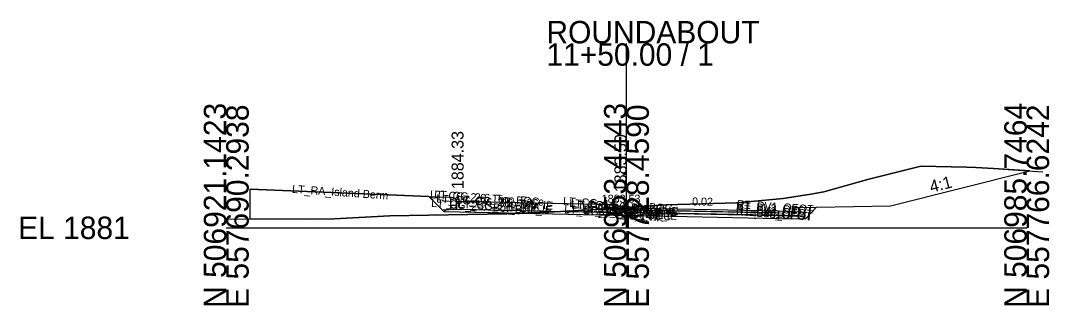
# Model space of a CAD drawing. Extents: x -36 to 140, y -10 to 2515.
# Drawn here: x -35.7 to 92.8, y 1490.3 to 1525.9 of the extents above; entities that cross this region are included whole.
import ezdxf

# ---------------------------------------------------------------- set-up
doc = ezdxf.new("R2010")
doc.units = 0
for name, color, linetype in [('Default', 7, 'Continuous'), ('Exist Cross Section Cell', 7, 'Continuous'), ('Exist XS Center Line Elevation Label', 7, 'Continuous'), ('Exist XS Ground Line', 7, 'Continuous'), ('Prop CMT Conc Surface', 7, 'Continuous'), ('Prop CMT Concrete Structures', 7, 'Continuous'), ('Prop CMT Pvmt Course 1', 7, 'Continuous'), ('Prop CMT Pvmt Course 1 CG', 7, 'Continuous'), ('Prop CMT Pvmt Course 2', 7, 'Continuous'), ('Prop CMT Pvmt Course 3', 7, 'Continuous'), ('Prop CMT Pvmt Course 4', 7, 'Continuous'), ('Prop CMT Slope Grass', 7, 'Continuous'), ('Prop CMT Subgrade Earthwork', 7, 'Continuous'), ('Prop Conc 4in Sidewalk', 7, 'Continuous'), ('Prop Conc Curb and Gutter', 7, 'Continuous'), ('Prop XS Earthwork Shape', 7, 'Continuous'), ('Prop XS Finish Grade Earthwork', 7, 'Continuous'), ('Prop XS Hydro Elevations', 7, 'Continuous'), ('Prop XS Side Slope Text', 7, 'Continuous'), ('Typical Structure Recommendation Sheet 1 CELL', 7, 'Continuous')]:
    doc.layers.add(name, color=color, linetype=linetype)

msp = doc.modelspace()

# ---------------------------------------------------------------- linework, layer by layer
at = {"layer": 'Exist Cross Section Cell'}
for p, q in [((40, 1500), (40, 1523.04)), ((-10, 1500), (40, 1500)), ((40, 1500), (90, 1500))]:
    msp.add_line(p, q, dxfattribs=at)
at = {"layer": 'Exist XS Ground Line'}
msp.add_lwpolyline([(-10, 1501.12), (0.01, 1501.08), (3.49, 1501.11), (10.45, 1501.51), (25.07, 1501.74), (30.26, 1501.97), (36.25, 1502.27), (40, 1502.53), (44.96, 1502.86), (53.77, 1503.13), (59.56, 1503.65), (63.04, 1504.2), (64.65, 1504.51), (70.29, 1506.06), (76.77, 1507.68), (82.46, 1507.56), (83.66, 1507.53), (85.87, 1507.39), (92.03, 1507)], dxfattribs=at)
at = {"layer": 'Prop CMT Conc Surface'}
for p, q in [((18.65, 1503.61), (18, 1503.82)), ((18, 1503.82), (18, 1502.82)), ((18, 1502.82), (18.75, 1502.82)), ((18, 1502.82), (18, 1502.32)), ((18.75, 1502.82), (18.75, 1503.47)), ((18.75, 1502.32), (18.75, 1502.82)), ((38.5, 1501.91), (38.5, 1502.91)), ((39.19, 1502.68), (38.5, 1502.91)), ((38.65, 1502.74), (38.56, 1502.74)), ((38.56, 1502.74), (38.64, 1502.66)), ((38.64, 1502.66), (38.65, 1502.74)), ((39.25, 1502.59), (39.25, 1502.6)), ((17.2, 1502.02), (17.5, 1502.32)), ((18, 1502.32), (17.5, 1502.32)), ((18, 1502.32), (18.75, 1502.32)), ((40, 1501.91), (38.5, 1501.91)), ((38.59, 1502.12), (38.52, 1502.11)), ((38.52, 1502.11), (38.55, 1502)), ((38.55, 1502), (38.59, 1502.12)), ((38.84, 1502.44), (38.89, 1502.29)), ((38.93, 1502.38), (38.84, 1502.44)), ((38.89, 1502.29), (38.93, 1502.38)), ((39.15, 1502.15), (39.24, 1502.1)), ((39.18, 1502.02), (39.15, 1502.15)), ((39.24, 1502.1), (39.18, 1502.02)), ((40, 1502.5), (39.34, 1502.5)), ((39.51, 1502.11), (39.43, 1502.09)), ((39.43, 1502.09), (39.47, 1501.98)), ((39.47, 1501.98), (39.51, 1502.11)), ((39.76, 1502.42), (39.81, 1502.27)), ((39.85, 1502.36), (39.76, 1502.42)), ((39.81, 1502.27), (39.85, 1502.36)), ((40, 1502.5), (40, 1501.91)), ((40, 1501.91), (40, 1502.49))]:
    msp.add_line(p, q, dxfattribs=at)
msp.add_lwpolyline([(40, 1501.92), (40, 1502.5)], dxfattribs=at)
msp.add_lwpolyline([(40, 1501.92), (40, 1502.5)], dxfattribs=at)
for centre in [(38.71, 1502.83), (38.74, 1502.54), (38.93, 1502.64), (39.06, 1502.66), (38.57, 1502.5), (38.58, 1502.39), (38.62, 1502.02), (38.64, 1502.24), (38.73, 1502.38), (38.76, 1501.98), (38.78, 1502.25), (38.79, 1502.15), (38.85, 1502.49), (38.93, 1502.22), (39.02, 1502.36), (39.03, 1501.96), (39.04, 1502.09), (39.04, 1502.5), (39.07, 1502.22), (39.11, 1502.41), (39.23, 1502.43), (39.26, 1502.33), (39.27, 1501.96), (39.35, 1502.1), (39.35, 1501.95), (39.37, 1502.41), (39.36, 1502.18), (39.39, 1502.38), (39.5, 1502.38), (39.54, 1502.01), (39.56, 1502.22), (39.65, 1502.36), (39.68, 1501.97), (39.7, 1502.23), (39.71, 1502.14), (39.77, 1502.48), (39.85, 1502.2), (39.94, 1502.35), (39.95, 1501.95), (39.96, 1502.07), (39.99, 1502.21)]:
    msp.add_circle(centre, 0.00635, dxfattribs=at)
for centre, radius, start, end in [((18.6, 1503.47), 0.146, 0, 71.5651), ((39.16, 1502.6), 0.0937, 0, 71.5651), ((39.34, 1502.59), 0.0937, 180, 270), ((38.53, 1501.92), 0.00635, 27.0386, 154.2416)]:
    msp.add_arc(centre, radius, start, end, dxfattribs=at)
at = {"layer": 'Prop CMT Concrete Structures'}
msp.add_lwpolyline([(59, 1502.12), (61, 1502.02), (61, 1502.52), (61.5, 1502.52)], dxfattribs=at)
at = {"layer": 'Prop CMT Pvmt Course 1'}
msp.add_line((40, 1502.5), (59, 1502.12), dxfattribs=at)
for points in [[(40, 1502.25), (40, 1502.5)], [(40, 1502.25), (40, 1502.5)], [(40, 1502.25), (40, 1502.5)], [(58, 1501.89), (40, 1502.25)], [(59, 1502.12), (59, 1501.87)], [(59, 1502.12), (59, 1501.87)]]:
    msp.add_lwpolyline(points, dxfattribs=at)
at = {"layer": 'Prop CMT Pvmt Course 1 CG'}
for points in [[(59, 1501.54), (62, 1501.5), (62.36, 1501.14)], [(59, 1501.29), (59, 1501.54)]]:
    msp.add_lwpolyline(points, dxfattribs=at)
at = {"layer": 'Prop CMT Pvmt Course 2'}
for points in [[(40, 1501.91), (40, 1502.25)], [(40, 1501.92), (40, 1502.25)], [(40, 1502.25), (59, 1501.87)], [(40, 1501.92), (40, 1502.25)], [(58, 1501.56), (40, 1501.92)]]:
    msp.add_lwpolyline(points, dxfattribs=at)
at = {"layer": 'Prop CMT Pvmt Course 3'}
for points in [[(40, 1501.92), (59, 1501.54)], [(59, 1501.54), (59, 1501.18)], [(59, 1501.54), (59, 1501.21)]]:
    msp.add_lwpolyline(points, dxfattribs=at)
at = {"layer": 'Prop CMT Pvmt Course 4'}
for points in [[(40, 1501.59), (40, 1501.59)], [(40, 1501.59), (40, 1501.59)], [(40, 1501.58), (40, 1501.58)], [(59, 1501.21), (59, 1501.21)], [(59, 1501.21), (59, 1501.21)]]:
    msp.add_lwpolyline(points, dxfattribs=at)
at = {"layer": 'Prop CMT Slope Grass'}
for p, q in [((72.99, 1502.75), (90.4, 1507.1)), ((-7, 1501.11), (-7, 1504.82)), ((63.73, 1502.56), (72.99, 1502.75))]:
    msp.add_line(p, q, dxfattribs=at)
msp.add_lwpolyline([(15.29, 1503.93), (-7, 1504.82)], dxfattribs=at)
at = {"layer": 'Prop CMT Subgrade Earthwork'}
for p, q in [((17.2, 1502.02), (15.29, 1503.93)), ((62.36, 1501.14), (63.73, 1502.56)), ((17.2, 1502.02), (38.5, 1501.58)), ((38.5, 1501.58), (39.98, 1501.58)), ((39.98, 1501.58), (59, 1501.18))]:
    msp.add_line(p, q, dxfattribs=at)
msp.add_lwpolyline([(59, 1501.18), (62.36, 1501.14)], dxfattribs=at)
at = {"layer": 'Prop Conc 4in Sidewalk'}
for p, q in [((18.75, 1503.32), (18.75, 1502.32)), ((18.75, 1503.32), (38.5, 1502.91)), ((18.75, 1502.32), (38.5, 1501.91))]:
    msp.add_line(p, q, dxfattribs=at)
at = {"layer": 'Prop Conc Curb and Gutter'}
for points in [[(59, 1502.12), (61, 1502.02), (61, 1502.52), (61.5, 1502.52)], [(61.5, 1502.52), (61.5, 1501.51), (59, 1501.54)], [(59, 1501.54), (59, 1502.12)]]:
    msp.add_lwpolyline(points, dxfattribs=at)
at = {"layer": 'Prop XS Earthwork Shape'}
for points in [[(39.98, 1501.58), (59, 1501.18), (62.36, 1501.14), (63.73, 1502.56), (72.99, 1502.75), (90.4, 1507.1), (85.87, 1507.39), (83.66, 1507.53), (82.46, 1507.56), (76.77, 1507.68), (70.29, 1506.06), (64.65, 1504.51), (63.04, 1504.2), (59.56, 1503.65), (53.77, 1503.13), (44.96, 1502.86), (40, 1502.53), (36.25, 1502.27), (30.26, 1501.97), (26.94, 1501.82), (38.5, 1501.58)], [(-7, 1501.11), (-7, 1504.82), (15.29, 1503.93), (17.2, 1502.02), (26.94, 1501.82), (25.07, 1501.74), (10.45, 1501.51), (3.49, 1501.11), (0.01, 1501.08)]]:
    msp.add_lwpolyline(points, close=True, dxfattribs=at)
at = {"layer": 'Prop XS Finish Grade Earthwork'}
for p, q in [((15.29, 1503.93), (18, 1503.82)), ((61.5, 1502.52), (63.73, 1502.56))]:
    msp.add_line(p, q, dxfattribs=at)

# ---------------------------------------------------------------- texts
at = {"layer": 'Default'}
msp.add_text('-', height=0.0001, dxfattribs=at).set_placement((0, 1501.16))
at = {"layer": 'Exist Cross Section Cell'}
for s, p in [('ROUNDABOUT', (30, 1523.04)), ('11+50.00 / 1', (30, 1520.24)), ('EL 1881', (-36, 1498.6))]:
    msp.add_text(s, height=2.8, dxfattribs=at).set_placement(p)
for s, p in [('N 506921.1423', (-10, 1490)), ('N 506953.4443', (40, 1490)), ('N 506985.7464', (90, 1490)), ('E 557690.2938', (-7.2, 1490)), ('E 557728.4590', (42.8, 1490)), ('E 557766.6242', (92.8, 1490))]:
    msp.add_text(s, height=2.8, rotation=90, dxfattribs=at).set_placement(p)
at = {"layer": 'Exist XS Center Line Elevation Label'}
msp.add_text('1883.53', height=1, dxfattribs=at).set_placement((36.91, 1503.14))
at = {"layer": 'Prop XS Hydro Elevations'}
for s, height, rotation, p in [('1884.33', 1.5, 90, (19.65, 1504.84)), ('1883.50', 1.5, 90, (40, 1504.44)), ('0.02', 1, 358.8542, (48.19, 1502.8))]:
    msp.add_text(s, height=height, rotation=rotation, dxfattribs=at).set_placement(p)
at = {"layer": 'Prop XS Side Slope Text'}
msp.add_text('4:1', height=1.5, rotation=14.0452, dxfattribs=at).set_placement((78.08, 1504.38))
at = {"layer": 'Typical Structure Recommendation Sheet 1 CELL'}
for s, p in [('LT_RA_Island Berm', (-1.8, 1504.37)), ('LT_CG_2-6_Top_BOC', (15.43, 1503.7)), ('LT_CG_2-6_Top_Face', (15.95, 1503.7)), ('LT_CG_2-6_Top_Gut', (16.21, 1503.18)), ('LT_CG_2-6_Top_IE', (18.8, 1503.1)), ('LT_CG_1-6_Top_BOC', (32.05, 1502.86)), ('LT_CG_2-6_Bot_BOC', (15.57, 1502.62)), ('LT_CG_2-6_Bot_IE', (18.94, 1502.51)), ('LT_CG_1-6_Bot_BOC', (32.19, 1501.84)), ('LT_CG_1-6_Top_Face', (32.82, 1502.61)), ('LT_CG_1-6_Top_Gut', (33.09, 1502.42)), ('LT_CG_1-6_Top_IE', (34.43, 1502.39)), ('LT_CG_1-6_Bot_IE', (34.57, 1501.8)), ('LT_MI_BOC', (35.04, 1502.07)), ('LT_PV2_PGL', (36.36, 1502.01)), ('LT_PV3_PGL', (36.36, 1501.67)), ('RT_PV2_OEOT', (53.66, 1502.24)), ('RT_PV3_OEOT', (53.66, 1501.9)), ('RT_PV4_OEOT', (53.66, 1501.57)), ('RT_Sub_OEOT', (53.68, 1501.57)), ('RT_PV1_OEOT', (53.78, 1502.48)), ('LT_PV4_PGL', (36.36, 1501.34)), ('LT_Sub_PGL', (36.38, 1501.34))]:
    msp.add_text(s, height=1, rotation=356, dxfattribs=at).set_placement(p)

doc.saveas('drawing.dxf')
